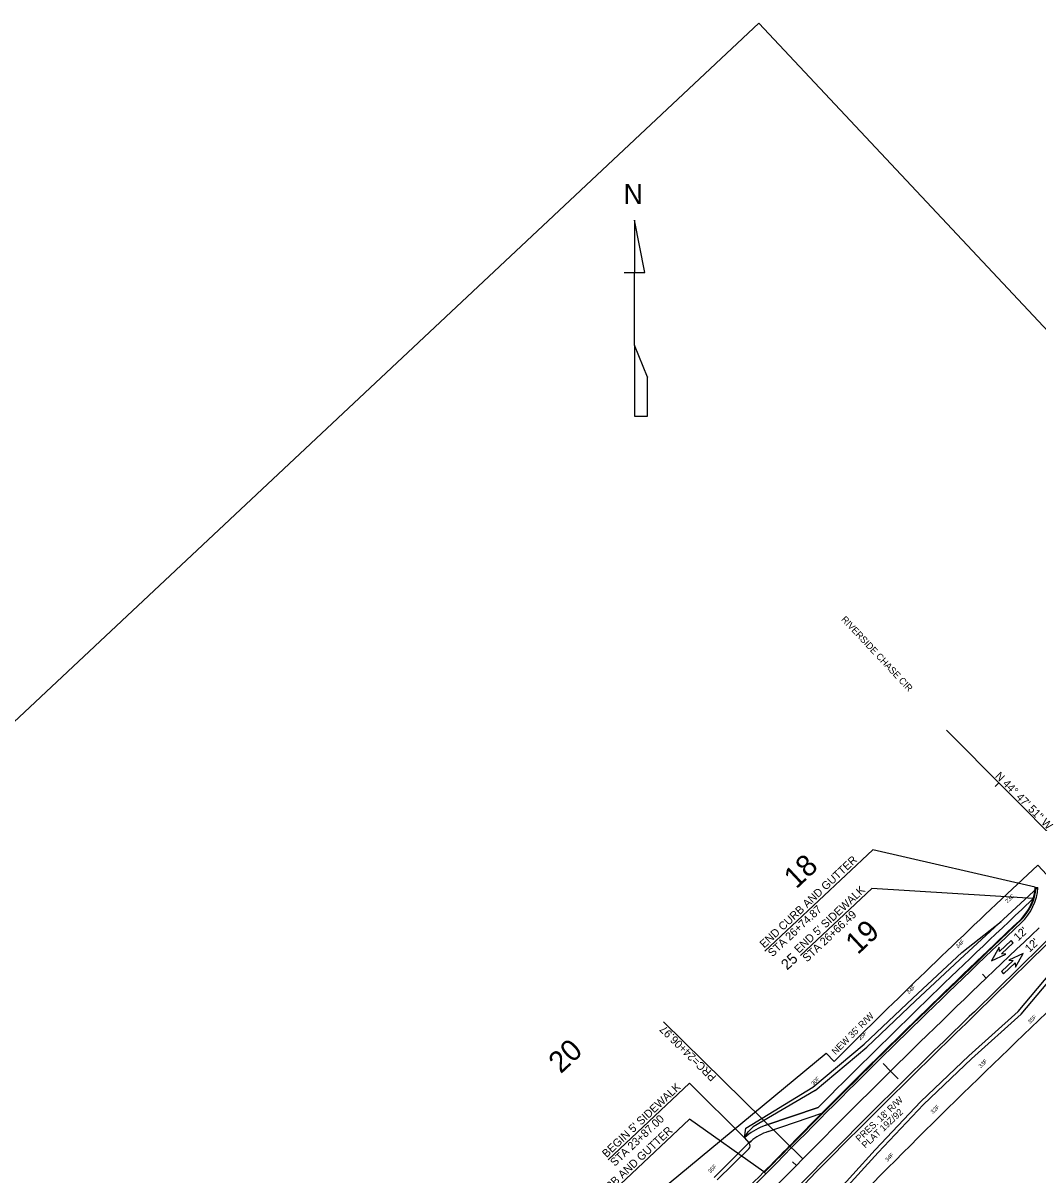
# Model space of a CAD drawing. Extents: x 1623239 to 1625698, y 1118659 to 1120751.
# Drawn here: x 1624068 to 1624829, y 1119863 to 1120726 of the extents above; entities that cross this region are included whole.
import ezdxf

# ---------------------------------------------------------------- set-up
doc = ezdxf.new("R2010")
doc.units = 0
for name, color, linetype in [('RD_EX_DV_TX_Prop', 7, 'Continuous'), ('RD_EX_Road Text', 7, 'Continuous'), ('RD_EX_RW_TX', 7, 'Continuous'), ('RD_HC_Cl', 7, 'Continuous'), ('RD_HC_CL_Rel', 7, 'Continuous'), ('RD_HC_Data', 7, 'Continuous'), ('RD_HC_Data_Tic', 7, 'Continuous'), ('RD_HC_TX_Sta50', 7, 'Continuous'), ('RD_PD_BOC', 7, 'Continuous'), ('RD_PD_CstnLmt', 7, 'Continuous'), ('RD_PD_CstnLmt_TX', 7, 'Continuous'), ('RD_PD_DR_ErosCtrl', 7, 'Continuous'), ('RD_PD_Final_TrvlWay', 7, 'Continuous'), ('RD_PD_Final_TX', 7, 'Continuous'), ('RD_PD_FOC', 7, 'Continuous'), ('RD_PD_PaveShd', 7, 'Continuous'), ('RD_PD_RW', 7, 'Continuous'), ('RD_PD_SW', 7, 'Continuous'), ('RD_SHT_ShtClip', 7, 'Continuous'), ('RD_SHT_TX', 7, 'Continuous')]:
    doc.layers.add(name, color=color, linetype=linetype)

msp = doc.modelspace()

# ---------------------------------------------------------------- linework, layer by layer
at = {"layer": 'RD_HC_Cl'}
msp.add_line((1624870.49, 1120085.68), (1624760.81, 1120196.14), dxfattribs=at)
at = {"layer": 'RD_HC_CL_Rel'}
for centre, start, end in [((1629271.64, 1115329.28), 133.267464, 135.457254), ((1620034.69, 1124419.96), 313.16267, 315.457254)]:
    msp.add_arc(centre, 6480, start, end, dxfattribs=at)
at = {"layer": 'RD_HC_Data'}
msp.add_line((1624653.16, 1119874.62), (1624548.65, 1119977.48), dxfattribs=at)
at = {"layer": 'RD_HC_Data_Tic'}
for p, q in [((1624800.03, 1120156.64), (1624797.19, 1120153.83)), ((1624790.59, 1120010.16), (1624787.83, 1120013.05)), ((1624718.89, 1119940.45), (1624713.27, 1119946.15)), ((1624724.51, 1119934.76), (1624718.89, 1119940.45)), ((1624648.27, 1119869.65), (1624645.42, 1119872.46))]:
    msp.add_line(p, q, dxfattribs=at)
at = {"layer": 'RD_PD_BOC'}
for p, q in [((1624827.4, 1120078.3), (1624829.4, 1120078.16)), ((1624623.87, 1119864.89), (1624625.29, 1119863.48))]:
    msp.add_line(p, q, dxfattribs=at)
for centre, radius, start, end in [((1624789.49, 1120080.85), 38, 313.32872, 356.15478), ((1629271.64, 1115329.28), 6494, 133.328722, 135.457254), ((1620034.69, 1124419.96), 6466, 315.213737, 315.457254)]:
    msp.add_arc(centre, radius, start, end, dxfattribs=at)
at = {"layer": 'RD_PD_CstnLmt'}
for p, q in [((1624774.24, 1120027.24), (1624829.4, 1120078.16)), ((1624814.53, 1119985.16), (1624863.65, 1120043.76)), ((1624737.54, 1119993), (1624774.24, 1120027.24)), ((1624701.1, 1119958.48), (1624737.54, 1119993)), ((1624777.49, 1119951.91), (1624814.53, 1119985.16)), ((1624662.36, 1119925.88), (1624701.1, 1119958.48)), ((1624741.53, 1119917.53), (1624777.49, 1119951.91)), ((1624662.36, 1119925.88), (1624615.73, 1119898.76)), ((1624707.3, 1119881.4), (1624741.53, 1119917.53)), ((1624612.01, 1119894.99), (1624615.73, 1119898.76)), ((1624609.35, 1119890.41), (1624612.01, 1119894.99)), ((1624588.92, 1119858.88), (1624612.6, 1119882.23)), ((1624612.8, 1119886.29), (1624612.56, 1119886.58)), ((1624673.75, 1119844.52), (1624707.3, 1119881.4))]:
    msp.add_line(p, q, dxfattribs=at)
msp.add_arc((1624610.49, 1119884.36), 3, 314.59399, 39.9134, dxfattribs=at)
at = {"layer": 'RD_PD_DR_ErosCtrl'}
for p, q in [((1624772.2, 1120029.43), (1624801.82, 1120052.7)), ((1624816.69, 1119983.07), (1624865.72, 1120041.56)), ((1624735.49, 1119995.19), (1624772.2, 1120029.43)), ((1624699.1, 1119960.71), (1624735.49, 1119995.19)), ((1624779.53, 1119949.71), (1624816.69, 1119983.07)), ((1624660.61, 1119928.32), (1624699.1, 1119960.71)), ((1624743.65, 1119915.41), (1624779.53, 1119949.71)), ((1624610.39, 1119897.64), (1624660.61, 1119928.32)), ((1624709.49, 1119879.36), (1624743.65, 1119915.41)), ((1624609.35, 1119890.41), (1624610.39, 1119897.64)), ((1624586.54, 1119860.74), (1624612.56, 1119886.58)), ((1624675.98, 1119842.52), (1624709.49, 1119879.36))]:
    msp.add_line(p, q, dxfattribs=at)
at = {"layer": 'RD_PD_Final_TrvlWay'}
msp.add_line((1624781.68, 1119984.95), (1624852.98, 1120055.09), dxfattribs=at)
for centre, radius, start, end in [((1624789.49, 1120080.85), 40, 313.32872, 356.15478), ((1629271.64, 1115329.28), 6492, 133.328722, 135.457254), ((1629271.64, 1115329.28), 6468, 133.961977, 135.457254), ((1620034.69, 1124419.96), 6468, 313.16267, 315.457254), ((1620034.69, 1124419.96), 6492, 313.16267, 315.457254)]:
    msp.add_arc(centre, radius, start, end, dxfattribs=at)
at = {"layer": 'RD_PD_Final_TX'}
for p, q in [((1624624.52, 1120030.39), (1624705.52, 1120106.35)), ((1624827.4, 1120078.3), (1624705.52, 1120106.35)), ((1624651.19, 1120027.23), (1624704.7, 1120077.41)), ((1624825.83, 1120069.74), (1624704.7, 1120077.41)), ((1624809.2, 1120038.28), (1624800.45, 1120030.08)), ((1624801.99, 1120028.44), (1624810.74, 1120036.64)), ((1624810.74, 1120036.64), (1624809.2, 1120038.28)), ((1624800.23, 1120033.37), (1624794.54, 1120023)), ((1624794.54, 1120023), (1624805.26, 1120028.01)), ((1624800.45, 1120030.08), (1624800.23, 1120033.37)), ((1624805.26, 1120028.01), (1624801.99, 1120028.44)), ((1624818.18, 1120028.71), (1624807.46, 1120023.7)), ((1624812.49, 1120018.33), (1624818.18, 1120028.71)), ((1624810.73, 1120023.27), (1624801.98, 1120015.06)), ((1624803.52, 1120013.42), (1624812.27, 1120021.63)), ((1624807.46, 1120023.7), (1624810.73, 1120023.27)), ((1624812.27, 1120021.63), (1624812.49, 1120018.33)), ((1624801.98, 1120015.06), (1624803.52, 1120013.42)), ((1624506.99, 1119874.02), (1624568.05, 1119931.28)), ((1624609.35, 1119890.41), (1624568.05, 1119931.28)), ((1624480.25, 1119821.93), (1624568.08, 1119904.3)), ((1624623.87, 1119864.89), (1624568.08, 1119904.3))]:
    msp.add_line(p, q, dxfattribs=at)
at = {"layer": 'RD_PD_FOC'}
for centre, radius, start, end in [((1624789.49, 1120080.85), 38.5, 313.32872, 356.15478), ((1629271.64, 1115329.28), 6493.5, 133.304383, 135.457254), ((1620034.69, 1124419.96), 6466.5, 315.213737, 315.457254)]:
    msp.add_arc(centre, radius, start, end, dxfattribs=at)
at = {"layer": 'RD_PD_PaveShd'}
msp.add_line((1624783.07, 1119983.52), (1624854.39, 1120053.67), dxfattribs=at)
for centre, radius, start, end in [((1629271.64, 1115329.28), 6466, 133.961889, 135.457254), ((1620034.69, 1124419.96), 6466, 313.75143, 315.213737), ((1620034.69, 1124419.96), 6494, 313.664525, 315.457254)]:
    msp.add_arc(centre, radius, start, end, dxfattribs=at)
at = {"layer": 'RD_PD_RW'}
for p, q in [((1624806.22, 1120073.26), (1624829.23, 1120094.92)), ((1624829.23, 1120094.92), (1624836.03, 1120087.7)), ((1624458.96, 1119778.79), (1624670.67, 1119953.92)), ((1624676.49, 1119947.71), (1624670.67, 1119953.92))]:
    msp.add_line(p, q, dxfattribs=at)
for radius, end in [(6515, 134.855208), (6430, 135.524786)]:
    msp.add_arc((1629271.64, 1115329.28), radius, 133.267464, end, dxfattribs=at)
at = {"layer": 'RD_PD_SW'}
for p, q in [((1624817.19, 1120061.61), (1624825.83, 1120069.74)), ((1624825.83, 1120069.74), (1624817.19, 1120061.61)), ((1624625.43, 1119899.89), (1624664.55, 1119913.14)), ((1624664.55, 1119913.14), (1624625.43, 1119899.89)), ((1624627.03, 1119895.16), (1624667.27, 1119908.78)), ((1624627.03, 1119895.16), (1624667.27, 1119908.78)), ((1624610.99, 1119891.79), (1624609.35, 1119890.41)), ((1624610.99, 1119891.79), (1624609.35, 1119890.41)), ((1624609.35, 1119890.41), (1624612.56, 1119886.58)), ((1624609.35, 1119890.41), (1624612.56, 1119886.58)), ((1624614.2, 1119887.95), (1624612.56, 1119886.58)), ((1624612.56, 1119886.58), (1624614.2, 1119887.95))]:
    msp.add_line(p, q, dxfattribs=at)
for centre, radius, start, end in [((1629271.64, 1115329.28), 6499, 133.267464, 135.144772), ((1629271.64, 1115329.28), 6499, 133.267464, 135.144772), ((1624789.49, 1120080.85), 38, 313.32872, 343.00314), ((1629271.64, 1115329.28), 6494, 133.328722, 135.155132), ((1624639.86, 1119857.27), 45, 108.70848, 129.9134), ((1624639.86, 1119857.27), 45, 108.70848, 129.9134), ((1624639.86, 1119857.27), 40, 108.70848, 129.9134), ((1624639.86, 1119857.27), 40, 108.70848, 129.9134)]:
    msp.add_arc(centre, radius, start, end, dxfattribs=at)
at = {"layer": 'RD_SHT_ShtClip'}
for p, q in [((1623307.11, 1119494.91), (1624620.05, 1120726.24)), ((1624620.05, 1120726.24), (1625372.53, 1119923.88))]:
    msp.add_line(p, q, dxfattribs=at)
at = {"layer": 'RD_SHT_TX'}
for p, q in [((1624534.63, 1120539.2), (1624526.79, 1120578.41)), ((1624526.79, 1120578.41), (1624526.79, 1120578.41)), ((1624526.79, 1120578.41), (1624526.79, 1120539.2)), ((1624518.95, 1120539.2), (1624526.79, 1120539.2)), ((1624526.79, 1120484.81), (1624526.79, 1120539.2)), ((1624526.79, 1120539.2), (1624534.63, 1120539.2)), ((1624534.63, 1120539.2), (1624534.63, 1120539.67)), ((1624536.59, 1120460.8), (1624526.79, 1120484.81)), ((1624526.79, 1120484.81), (1624526.79, 1120431.4)), ((1624536.59, 1120431.4), (1624536.59, 1120461.07)), ((1624536.59, 1120461.07), (1624536.59, 1120460.8)), ((1624526.79, 1120431.4), (1624536.59, 1120431.4))]:
    msp.add_line(p, q, dxfattribs=at)

# ---------------------------------------------------------------- texts
at = {"layer": 'RD_EX_DV_TX_Prop'}
for s, p in [('18', (1624648.09, 1120076.51)), ('19', (1624694.26, 1120027.28)), ('20', (1624471.56, 1119938))]:
    msp.add_text(s, height=16, rotation=43.16267, dxfattribs=at).set_placement(p)
at = {"layer": 'RD_EX_Road Text'}
msp.add_text('RIVERSIDE CHASE CIR', height=5, rotation=313.16267, dxfattribs=at).set_placement((1624681.54, 1120278.74))
at = {"layer": 'RD_EX_RW_TX'}
for s, p in [("PRES. 18' R/W", (1624695.46, 1119887.06)), ('PLAT 19Z/92', (1624700.02, 1119882.19))]:
    msp.add_text(s, height=5, rotation=43.16267, dxfattribs=at).set_placement(p)
at = {"layer": 'RD_HC_Data'}
for s, rotation, p in [('N 44%%d 47\' 51" W', 314.79754, (1624796.87, 1120161.25)), ('PRC=24+06.97', 135.45725, (1624588.7, 1119936.48))]:
    msp.add_text(s, height=6, rotation=rotation, dxfattribs=at).set_placement(p)
at = {"layer": 'RD_HC_TX_Sta50'}
msp.add_text('25', height=8, rotation=42.92763, dxfattribs=at).set_placement((1624641.24, 1120015.72))
at = {"layer": 'RD_PD_CstnLmt_TX'}
for s, rotation, p in [('23C', 43.3084, (1624806.53, 1120066.15)), ('24F', 43.7505, (1624769.4, 1120032.3)), ('24F', 44.19259, (1624732.66, 1119998.02)), ('35F', 43.7505, (1624823.51, 1119975.77)), ('25F', 44.63469, (1624696.18, 1119963.46)), ('33F', 44.19259, (1624786.55, 1119942.59)), ('30F', 45.07679, (1624661.09, 1119929.44)), ('32F', 44.63469, (1624750.66, 1119908.28)), ('34F', 45.07679, (1624716.5, 1119872.22)), ('35F', 44.95352, (1624583.7, 1119863.56))]:
    msp.add_text(s, height=3, rotation=rotation, dxfattribs=at).set_placement(p)
at = {"layer": 'RD_PD_Final_TX'}
for s, rotation, p in [('END CURB AND GUTTER', 43.16253, (1624624.12, 1120032.28)), ("END 5' SIDEWALK", 43.16253, (1624650.06, 1120028.43)), ('STA 26+74.87', 43.16253, (1624630.28, 1120025.71)), ('STA 26+66.49', 43.16253, (1624656.22, 1120021.87)), ("12'", 43.16341, (1624814.51, 1120037.61)), ("12'", 43.16341, (1624822.99, 1120029.11)), ("BEGIN 5' SIDEWALK", 43.16253, (1624505.87, 1119875.22)), ('STA 23+87.00', 43.16253, (1624512.02, 1119868.66)), ('BEGIN CURB AND GUTTER', 43.16253, (1624479.85, 1119823.82))]:
    msp.add_text(s, height=6, rotation=rotation, dxfattribs=at).set_placement(p)
at = {"layer": 'RD_PD_RW'}
msp.add_text("NEW 35' R/W", height=5, rotation=44.81892, dxfattribs=at).set_placement((1624677.66, 1119952.39))
at = {"layer": 'RD_SHT_TX'}
msp.add_text('N', height=15, rotation=0, dxfattribs=at).set_placement((1624518.64, 1120590.62))

doc.saveas('drawing.dxf')
